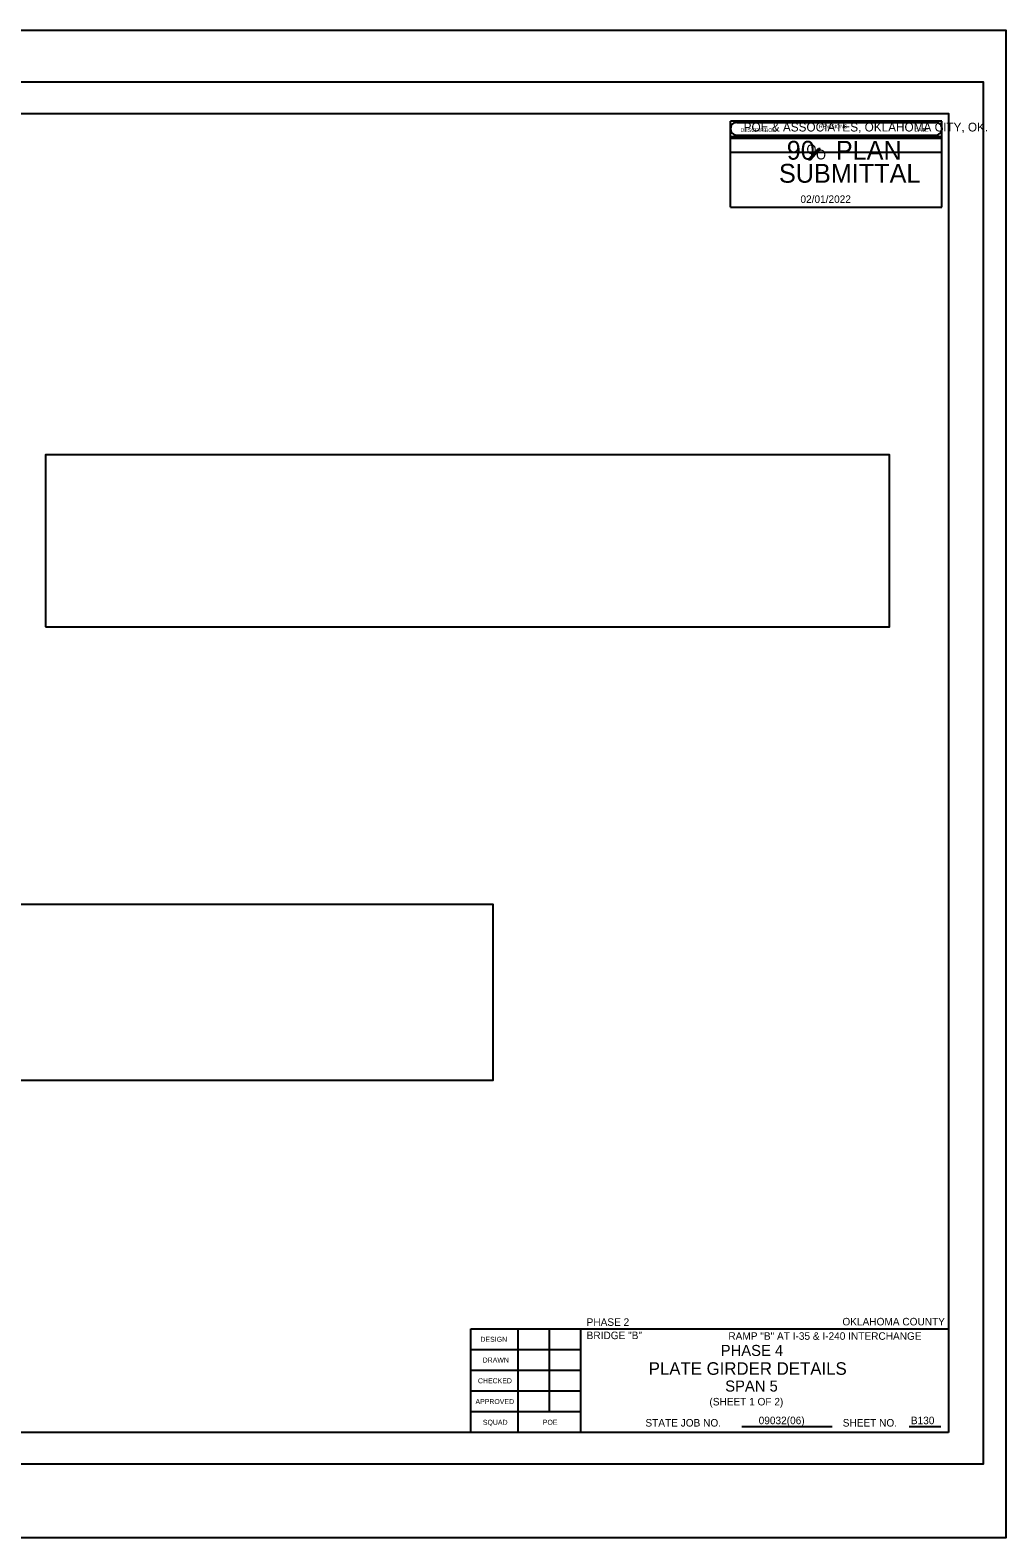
# Model space of a CAD drawing. Extents: x 4944 to 17449, y 3824 to 49087.
# Drawn here: x 8063 to 9553, y 14341 to 16645 of the extents above; entities that cross this region are included whole.
import ezdxf

# ---------------------------------------------------------------- set-up
doc = ezdxf.new("R2010")
doc.units = 0
for name, color, linetype in [('37_S_TXT', 7, 'Continuous'), ('3A', 7, 'Continuous'), ('BEAM', 7, 'Continuous'), ('DIM', 7, 'Continuous'), ('ID', 7, 'Continuous'), ('Level 14', 7, 'Continuous'), ('Level 17', 7, 'Continuous'), ('Level 36', 7, 'Continuous'), ('REVISED', 7, 'Continuous')]:
    doc.layers.add(name, color=color, linetype=linetype)

msp = doc.modelspace()

# ---------------------------------------------------------------- linework, layer by layer
at = {"layer": '37_S_TXT'}
msp.add_lwpolyline([(6097.3, 16645.4), (9553.3, 16645.4), (9553.3, 14341.3), (6097.3, 14341.3)], close=True, dxfattribs=at)
at = {"layer": '3A'}
for points in [[(8086.5, 15733.7), (9375.7, 15733.7), (9375.7, 15996.2), (8086.5, 15996.2)], [(7849.2, 15040.9), (8770.3, 15040.9), (8770.3, 15309.3), (7849.2, 15309.3)]]:
    msp.add_lwpolyline(points, close=True, dxfattribs=at)
at = {"layer": 'DEFPOINTS'}
for p, q in [((9455.7, 16506.2), (9132.6, 16506.2)), ((9132.6, 16458.2), (9132.6, 16506.2)), ((9455.7, 16458.2), (9455.7, 16506.2)), ((9455.7, 16482.2), (9132.6, 16482.2)), ((9455.7, 16458.2), (9132.6, 16458.2))]:
    msp.add_line(p, q, dxfattribs=at)
at = {"layer": 'DIM'}
msp.add_lwpolyline([(6254.5, 16566.2), (9518.5, 16566.2), (9518.5, 14454.1), (6254.5, 14454.1)], close=True, dxfattribs=at)
at = {"layer": 'Level 14'}
for p, q in [((8736.1, 14502.1), (8736.1, 14660.6)), ((8736.1, 14660.6), (9465.7, 14660.6)), ((8904, 14502.1), (8904, 14660.6)), ((8904.1, 14502.1), (8904.1, 14660.6))]:
    msp.add_line(p, q, dxfattribs=at)
msp.add_lwpolyline([(9465.7, 14502.1), (6441.7, 14502.1), (6441.7, 16518.2), (9465.7, 16518.2)], close=True, dxfattribs=at)
at = {"layer": 'Level 17'}
for p, q in [((8808.1, 14502.1), (8808.1, 14660.6)), ((8856.1, 14533.8), (8856.1, 14660.6)), ((9149.9, 14511.4), (9288.2, 14511.4)), ((9149.9, 14511.4), (9288.2, 14511.4)), ((9405.7, 14511.4), (9453.9, 14511.4)), ((9405.7, 14511.4), (9453.9, 14511.4))]:
    msp.add_line(p, q, dxfattribs=at)
for points in [[(8904, 14628.9), (8736.1, 14628.9)], [(8904, 14597.2), (8736.1, 14597.2)], [(8904, 14565.5), (8736.1, 14565.5)], [(8904, 14533.8), (8736.1, 14533.8)]]:
    msp.add_lwpolyline(points, dxfattribs=at)
at = {"layer": 'Level 36'}
for p, q in [((9142.2, 16504.2), (9446.1, 16504.2)), ((9132.6, 16480.2), (9455.7, 16480.2)), ((9132.6, 16374.7), (9132.6, 16480.2)), ((9142.2, 16485), (9446.1, 16485)), ((9455.7, 16374.7), (9455.7, 16480.2)), ((9252, 16447.8), (9266.9, 16464.3)), ((9253.7, 16447.8), (9268.6, 16464.3)), ((9254.2, 16447.8), (9269.1, 16464.3)), ((9254.9, 16447.8), (9269.8, 16464.3)), ((9266.9, 16464.3), (9269.8, 16464.3)), ((9252, 16447.8), (9254.9, 16447.8)), ((9132.6, 16374.7), (9455.7, 16374.7))]:
    msp.add_line(p, q, dxfattribs=at)
for centre, start, end in [((9142.2, 16494.7), 89.9952, 270), ((9446.2, 16494.7), 270, 90.0048)]:
    msp.add_arc(centre, 9.6, start, end, dxfattribs=at)

# ---------------------------------------------------------------- texts
at = {"layer": '3A'}
for s, height, p in [('PHASE 2', 11.52, (8912.9, 14665.3)), ('OKLAHOMA COUNTY', 11.52, (9303.6, 14666)), ('BRIDGE "B"', 11.52, (8912.9, 14645)), ('RAMP "B" AT I-35 & I-240 INTERCHANGE', 11.52, (9129.4, 14644)), ('(SHEET 1 OF 2)', 11.5, (9100.5, 14543.7)), ('09032(06)', 11.52, (9175.7, 14515)), ('B130', 11.52, (9408.2, 14515))]:
    msp.add_text(s, height=height, dxfattribs=at).set_placement(p)
at = {"layer": 'BEAM'}
msp.add_text('PLATE GIRDER DETAILS', height=19.2, dxfattribs=at).set_placement((9007.7, 14590.5))
at = {"layer": 'DEFPOINTS'}
for s, height, p in [('REVISIONS', 5.76, (9267.8, 16495.4)), ('DESCRIPTION', 5.76, (9148, 16489.8)), ('DATE', 5.76, (9413.8, 16490.2)), ('PHASE 4', 16.88, (9117.8, 14619.3))]:
    msp.add_text(s, height=height, dxfattribs=at).set_placement(p)
at = {"layer": 'ID'}
msp.add_text('SPAN 5', height=16.88, dxfattribs=at).set_placement((9124.6, 14564.9))
at = {"layer": 'Level 36'}
for s, height, p in [('POE & ASSOCIATES, OKLAHOMA CITY, OK.', 13.44, (9152.8, 16490.5)), ('90   PLAN', 28.8, (9218.6, 16447.4)), ('O', 14.7, (9248.7, 16455.9)), ('O', 14.7, (9263.3, 16447.8)), ('SUBMITTAL', 28.8, (9206.7, 16412.2)), ('02/01/2022', 11.52, (9239.5, 16381.3))]:
    msp.add_text(s, height=height, dxfattribs=at).set_placement(p)
at = {"layer": 'REVISED'}
for s, height, p in [('DESIGN', 7.68, (8750.7, 14640.9)), ('DRAWN', 7.68, (8754.1, 14609.2)), ('CHECKED', 7.68, (8746.9, 14577.5)), ('APPROVED', 7.68, (8743.1, 14545.8)), ('SQUAD', 7.68, (8754.4, 14514.1)), ('POE', 7.68, (8846, 14514.1)), ('STATE JOB NO.', 11.52, (9002.7, 14511.4)), ('STATE JOB NO.', 11.52, (9002.7, 14511.4)), ('SHEET NO. ', 11.52, (9304.1, 14511.4)), ('SHEET NO. ', 11.52, (9304.1, 14511.4))]:
    msp.add_text(s, height=height, dxfattribs=at).set_placement(p)

doc.saveas('drawing.dxf')
